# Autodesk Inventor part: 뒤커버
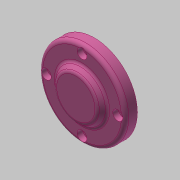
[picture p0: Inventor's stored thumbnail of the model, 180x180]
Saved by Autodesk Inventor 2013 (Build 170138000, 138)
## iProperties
Created: 2017-08
Part Number: 뒤커버
Material: 알루미늄 6061
Document SubType Name: Modeling
Designer: mduedu
Density: 2.71 g/cm^3
Mass: 99.1181 g
Surface Area: 135.95 cm^2
Volume: 36.5749 cm^3
Author: mduedu
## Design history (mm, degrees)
sketch "스케치1"
  geometry: C1 r 35 at (0, 0); 1 further point
  constraints: 1 centre point, 1 coincident
  dimensions: "d0" = 70 diameter of C1
extrude "돌출1" new body sketch "스케치1" distance "d1" = 10; taper "d2" = 0 deg
sketch "스케치2"
  geometry: C1 r 21 at (0, 0); 1 further point
  constraints: 1 centre point, 1 coincident
  dimensions: "d3" = 42 diameter of C1
node "작업 평면1"
sketch "스케치3"
  geometry: C1 r 17 at (0, 0); 1 further point
  constraints: 1 centre point, 1 coincident
  dimensions: "d5" = 34 diameter of C1
feature "로프트1" sketch "스케치3" dims "d6" = 0, "d7" = 90 deg, "d8" = 0, "d9" = 90 deg
sketch "스케치4"
  geometry: C1 r 24 at (0, 0); 1 further point
  constraints: 1 centre point, 1 coincident
  dimensions: "d65" = 48 diameter of C1
extrude "돌출2" join sketch "스케치4" distance "d10" = 8; taper "d11" = 0 deg
hole "구멍1" diameter "d14" = 40; stored, may be unused: countersink angle "d18" = 90 deg, drill point angle "d20" = 0 deg; dims "d15" = 6, "d16" = 4, "d17" = 2, "d19" = 12, "d66" = 10, "d67" = 10
hole "구멍2" diameter "d23" = 34; stored, may be unused: countersink angle "d27" = 90 deg, drill point angle "d29" = 0 deg; dims "d24" = 6, "d25" = 4, "d26" = 2, "d28" = 6, "d62" = 10, "d63" = 10
chamfer "모따기1" distance "d39" = 1; stored, may be unused: second distance "d40" = 2, angle "d41" = 45 deg
fillet "모깎기1" dims "d42" = 0.3
fillet "모깎기2" dims "d43" = 3
sketch "스케치5" dims "d44" = 58
  geometry: 6 further points
  constraints: 2 vertical alignment, 1 coincident, 7 other
  dimensions: "d47" = 360 deg dimension on point (0, 0) point (0, 29) (derived)
sketch "스케치6" dims "d64" = 58 (derived)
  geometry: 6 further points
  constraints: 1 coincident, 1 vertical alignment, 6 other
hole "구멍4" sketch "스케치6" at (0, 29), (-29, 0), (29, 0), (0, -29) diameter "d49" = 4.5; stored, may be unused: countersink angle "d53" = 90 deg, drill point angle "d55" = 0 deg; dims "d50" = 6, "d51" = 8, "d52" = 4.6, "d54" = 8
fillet "모깎기3" dims "d56" = 3
fillet "모깎기4" dims "d57" = 3
fillet "모깎기5" dims "d58" = 3
node "솔리드1"
other parameters: "d4" = 5
